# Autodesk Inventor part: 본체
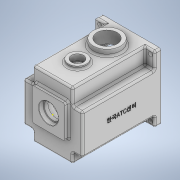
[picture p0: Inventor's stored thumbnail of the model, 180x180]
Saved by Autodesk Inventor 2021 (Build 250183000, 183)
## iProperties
Created: 2022-08
Part Number: 본체
Material: 일반
Document SubType Name: Modeling
Designer: Owner
Mass: 1344.69 g
Surface Area: 1181.31 cm^2
Volume: 498.035 cm^3
Density: 2.7 g/cm^3
Appearance: 기본값
Author: Owner
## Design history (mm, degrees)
sketch "스케치1"
  geometry: L1 (-49, -55)-(49, -55); L2 (49, -55)-(49, 55); L3 (49, 55)-(-49, 55); L4 (-49, 55)-(-49, -55); L5 (-49, -55)-(49, 55); L6 (49, -55)-(-49, 55); 1 further point
  constraints: 12 end point, 2 midpoint, 2 parallel, 1 horizontal, 1 perpendicular
  dimensions: "d0" = 110 distance between parallel lines of L1 L3; "d1" = 98 distance between parallel lines of L2 L4
extrude "돌출1" new body sketch "스케치1" distance "d2" = 130; taper "d3" = 0 deg
sketch "스케치2"
  geometry: L1 (-49, -55)-(-49, 55) reference; L2 (-49, 55)-(-33, 55); L3 (-33, 55)-(-33, 28); L4 (-33, 28)-(-49, 28); L5 (-49, 28)-(-49, 55); 2 further points
  constraints: 8 end point, 2 parallel, 1 horizontal, 1 perpendicular
  dimensions: "d4" = 27 distance between parallel lines of L4 L2; "d5" = 16 distance between parallel lines of L3 L1
extrude "돌출2" cut sketch "스케치2" distance "d6" = 120; taper "d7" = 0 deg
sketch "스케치3"
  geometry: L1 (-27, -21)-(27, -21); L2 (27, -21)-(27, 33); L3 (27, 33)-(-27, 33); L4 (-27, 33)-(-27, -21); L5 (-49, -55)-(49, -55) reference; 2 further points
  constraints: 8 end point, 2 parallel, 1 horizontal, 1 midpoint, 1 perpendicular, 1 vertical alignment
  dimensions: "d8" = 54 distance between parallel lines of L1 L3; "d9" = 54 distance between parallel lines of L2 L4; "d191" = 88 distance between parallel lines of L5 L3
extrude "돌출3" join sketch "스케치3" distance "d10" = 7; taper "d11" = 0 deg
sketch "스케치4"
  geometry: L1 (82, -130)-(16, -130) reference; L2 (0, 0)-(98, 0) reference; C1 r 15 at (49, -89); C2 r 22.5 at (49, -40); 3 further points
  constraints: 2 centre point, 2 midpoint, 2 vertical alignment
  dimensions: "d12" = 30 diameter of C1; "d13" = 45 diameter of C2; "d14" = 49 distance of C2.centre C1.centre; "d15" = 40 distance from line of L2 C2.centre
extrude "돌출4" join sketch "스케치4" distance "d16" = 5; taper "d17" = 0 deg
extrude "돌출5" join sketch "스케치4" distance "d18" = 10; taper "d19" = 0 deg
sketch "스케치5"
  geometry: L1 (49, -55)-(-49, -55) reference; L2 (-49, -55)-(-33, -55); L3 (-33, -55)-(-33, -38); L4 (-33, -38)-(-49, -38); L5 (-49, -38)-(-49, -55); 2 further points
  constraints: 8 end point, 2 parallel, 1 horizontal, 1 perpendicular
  dimensions: "d20" = 17 distance between parallel lines of L1 L4; "d21" = 16 distance between parallel lines of L5 L3
extrude "돌출6" cut sketch "스케치5" distance "d22" = 120; taper "d23" = 0 deg
sketch "스케치7"
  geometry: 1 further point
sketch "스케치15"
  geometry: L1 (-49, -55)-(49, -55) reference; L2 (-23, 33.249)-(-23, 45); L3 (-23, 45)-(23, 45); L4 (23, 45)-(23, 33.249); A1 r 42 centre (0, -5) between (-25.375, 28.468) and (25.375, 28.468); A2 r 6 centre (-29, 33.249) between (-25.375, 28.468) and (-23, 33.249); A3 r 6 centre (29, 33.249) between (23, 33.249) and (25.375, 28.468); 3 further points
  constraints: 8 point on circle, 6 end point, 4 tangent, 3 centre point, 2 perpendicular, 2 point on line, 1 parallel, 1 vertical, 1 vertical alignment
  dimensions: "d33" = 50 distance from line of L1 A1.centre; "d34" = 84 diameter of A1; "d35" = 46 distance between parallel lines of L4 L2; "d37" = 6 radius of A2; "d38" = 6 radius of A3 (derived); "d196" = 50 distance from line of L3 A1.centre
extrude "돌출9" cut sketch "스케치15" distance "d39" = 121; taper "d40" = 0 deg
sketch "스케치17"
  geometry: L1 (23, 45)-(23, 33.249) reference; L2 (-23, 45)-(23, 45) reference; L3 (-23, 33.249)-(-23, 45) reference; L4 (-26, 33.249)-(-26, 48); L5 (-26, 48)-(26, 48); L6 (26, 48)-(26, 33.249); A1 r 42 centre (0, -5) between (-25.375, 28.468) and (25.375, 28.468) reference; A2 r 6 centre (-29, 33.249) between (-25.375, 28.468) and (-23, 33.249) reference; A3 r 6 centre (29, 33.249) between (23, 33.249) and (25.375, 28.468) reference; A4 r 45 centre (0, -5) between (-27.188, 30.859) and (27.188, 30.859); A5 r 3 centre (-29, 33.249) between (-27.188, 30.859) and (-26, 33.249); A6 r 3 centre (29, 33.249) between (26, 33.249) and (27.188, 30.859); 1 further point
  constraints: 6 end point, 6 point on circle, 3 centre point, 5 other
  dimensions: "d41" = 3 radial gap between concentric circles of A1 A4
extrude "돌출11" cut sketch "스케치17" distance "d44" = 9; taper "d45" = 0 deg
sketch "스케치19" dims "d52" = 72
  geometry: L1 (33, -55)-(-33, -55) reference; L2 (36, -1)-(41.809, -1); L3 (36, -9)-(41.809, -9); A1 r 42 centre (0, -5) between (-25.375, 28.468) and (25.375, 28.468) reference; A2 r 4 centre (36, -5) between (36, -1) and (36, -9); 2 further points
  constraints: 4 end point, 4 point on circle, 2 horizontal, 2 tangent, 1 centre point, 1 horizontal alignment, 1 parallel, 1 vertical alignment, 2 other
  dimensions: "d51" = 50 distance from line of L1 point (0, -5); "d53" = 8 diameter of A2
extrude "돌출12" join sketch "스케치19" distance "d55" = 121; taper "d56" = 0 deg
sketch "스케치21"
  geometry: A1 r 4 centre (36, -5) between (36, -1) and (36, -9) reference; 2 further points
  constraints: 1 coincident
hole "구멍1" sketch "스케치21" at (36, -5) diameter "d57" = 3.242; stored, may be unused: countersink angle "d61" = 90 deg, drill point angle "d63" = 118 deg; dims "d58" = 7, "d59" = 4, "d60" = 2, "d62" = 9
sketch "스케치24"
  geometry: C1 r 22.5 at (0, 0) reference; 2 further points
  constraints: 1 coincident
hole "구멍4" sketch "스케치24" at (0, 0) diameter "d78" = 33.376; stored, may be unused: countersink angle "d82" = 90 deg, drill point angle "d84" = 0 deg; dims "d79" = 70, "d80" = 4, "d81" = 2, "d83" = 77.3
sketch "스케치27"
  geometry: A1 r 21 centre (0, 6) between (8.978, -12.984) and (-8.978, -12.984); A2 r 15 centre (0, -25) between (-8.978, -12.984) and (8.978, -12.984); A3 r 4 centre (36, -5) between (36, -1) and (36, -9) reference; 1 further point
  constraints: 4 point on circle, 2 centre point, 2 vertical alignment
  dimensions: "d95" = 42 diameter of A1; "d96" = 30 diameter of A2; "d98" = 20 vertical distance of A2.centre A3.centre; "d102" = 11 vertical distance of A3.centre A1.centre
extrude "돌출13" join sketch "스케치27" distance "d100" = 7; taper "d101" = 0 deg
sketch "스케치30"
  geometry: L1 (-33, -55)-(33, -55) reference; C1 r 14 at (0, 6); 1 further point
  constraints: 1 centre point, 1 vertical alignment
  dimensions: "d103" = 61 distance from line of L1 C1.centre; "d104" = 28 diameter of C1
extrude "돌출14" cut sketch "스케치30" distance "d105" = 100; taper "d106" = 0 deg
sketch "스케치31"
  geometry: C1 r 14 at (0, 6) reference; 2 further points
  constraints: 1 coincident
hole "구멍6" sketch "스케치31" at (0, 6) diameter "d107" = 32; stored, may be unused: countersink angle "d111" = 90 deg, drill point angle "d113" = 0 deg; dims "d108" = 70, "d109" = 4, "d110" = 2, "d112" = 7
sketch "스케치32"
  geometry: C1 r 9.5 at (0, -25); A1 r 15 centre (0, -25) between (-8.978, -12.984) and (8.978, -12.984) reference; 1 further point
  constraints: 1 centre point, 1 coincident
  dimensions: "d114" = 19 diameter of C1
extrude "돌출15" cut sketch "스케치32" distance "d115" = 10; taper "d116" = 0 deg
sketch "스케치33"
  geometry: C1 r 9.5 at (0, -25) reference; 2 further points
  constraints: 1 coincident
hole "구멍7" sketch "스케치33" at (0, -25) diameter "d117" = 22; stored, may be unused: countersink angle "d121" = 90 deg, drill point angle "d123" = 0 deg; dims "d118" = 70, "d119" = 4, "d120" = 2, "d122" = 7
fillet "모깎기1" dims "d124" = 3
chamfer "모따기1" distance "d125" = 1; stored, may be unused: second distance "d126" = 2, angle "d127" = 45 deg
fillet "모깎기7" dims "d133" = 3
fillet "모깎기8" dims "d134" = 3
fillet "모깎기14" dims "d140" = 3
sketch "스케치34"
  geometry: C1 r 15 at (0, 0) reference; C2 r 10 at (0, 0); 1 further point
  constraints: 1 centre point, 1 coincident
  dimensions: "d141" = 20 diameter of C2
extrude "돌출16" cut sketch "스케치34" stored distance "d142" = 7; taper "d143" = 0 deg
fillet "모깎기15" dims "d144" = 3
sketch "스케치35"
  geometry: C1 r 10 at (23, -32) reference; 2 further points
  constraints: 1 coincident
hole "구멍8" sketch "스케치35" at (23, -32) diameter "d145" = 30; stored, may be unused: countersink angle "d149" = 90 deg, drill point angle "d151" = 0 deg; dims "d146" = 70, "d147" = 4, "d148" = 2, "d150" = 5
fillet "모깎기16" dims "d152" = 0.3
sketch "스케치36"
  geometry: L1 (49, 55)-(-49, 55) reference; L2 (-49, 55)-(-49, -55) reference; C1 r 3.5 at (-42, 48); 1 further point
  constraints: 1 centre point
  dimensions: "d153" = 7 distance from line of L1 C1.centre; "d154" = 7 distance from line of L2 C1.centre; "d155" = 7 diameter of C1
extrude "돌출17" cut sketch "스케치36" distance "d156" = 10; taper "d157" = 0 deg
sketch "스케치37"
  geometry: L1 (-130, 83)-(-130, 110) reference; L2 (-10, 83)-(-130, 83) reference; 2 further points
  constraints: 1 other
  dimensions: "d164" = 65 distance from line of L1 point (-65, 50); "d165" = 33 distance from line of L2 point (-65, 50)
feature "엠보싱1" sketch "스케치37" dims "d166" = 0.5, "d167" = 0
fillet "모깎기17" dims "d171" = 3
fillet "모깎기18" dims "d172" = 3
fillet "모깎기19" dims "d173" = 3
fillet "모깎기20" dims "d174" = 3
fillet "모깎기21" dims "d175" = 3
fillet "모깎기22" dims "d176" = 3
fillet "모깎기23" dims "d177" = 3
fillet "모깎기24" dims "d178" = 3
fillet "모깎기25" dims "d179" = 3
sketch "스케치38"
  geometry: C1 r 14 at (0, 6) reference; 2 further points
  constraints: 1 coincident
hole "구멍9" sketch "스케치38" at (0, 6) diameter "d180" = 35; stored, may be unused: countersink angle "d184" = 90 deg, drill point angle "d186" = 0 deg; dims "d181" = 70, "d182" = 4, "d183" = 2, "d185" = 10
fillet "모깎기26" dims "d187" = 3
fillet "모깎기27" dims "d188" = 3
fillet "모깎기28" dims "d189" = 3
fillet "모깎기29" dims "d190" = 3
chamfer "모따기3" distance "d192" = 0.8; stored, may be unused: second distance "d193" = 2, angle "d194" = 30 deg
fillet "모깎기30" dims "d195" = 3
fillet "모깎기31" dims "d197" = 3
chamfer "모따기4" distance "d198" = 1; stored, may be unused: second distance "d199" = 2, angle "d200" = 30 deg
node "솔리드1"
mirror "미러1"
mirror "미러3"
mirror "미러5"
pattern_linear "직사각형 패턴1" dims "d160" = 96
pattern_linear "직사각형 패턴2" dims "d163" = 84
feature "A9D066F2-1C7D-4E18-AEED-F7BC21143FA4" dims "d107" = 32, "d108" = 70, "d109" = 4, "d110" = 2, "d111" = 90 deg, "d112" = 7, "d113" = 0
